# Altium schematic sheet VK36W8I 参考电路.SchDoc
size A4; PageSetup: Record=PageOptions¦CenterHorizontal=True¦CenterVertical=True¦PrintScale=1.00¦XCorrection=1.00¦YCorrection=1.00¦PrintKind=0¦BorderSize=5000000¦LeftOffset=0¦BottomOffset=0¦Orientation=2¦PaperLength=1000¦PaperWidth=1000¦Scale=100¦PaperSource=7¦PrintQuality=-4¦MediaType=1¦DitherType=10¦PaperKind=A4¦PrintScaleMode=1
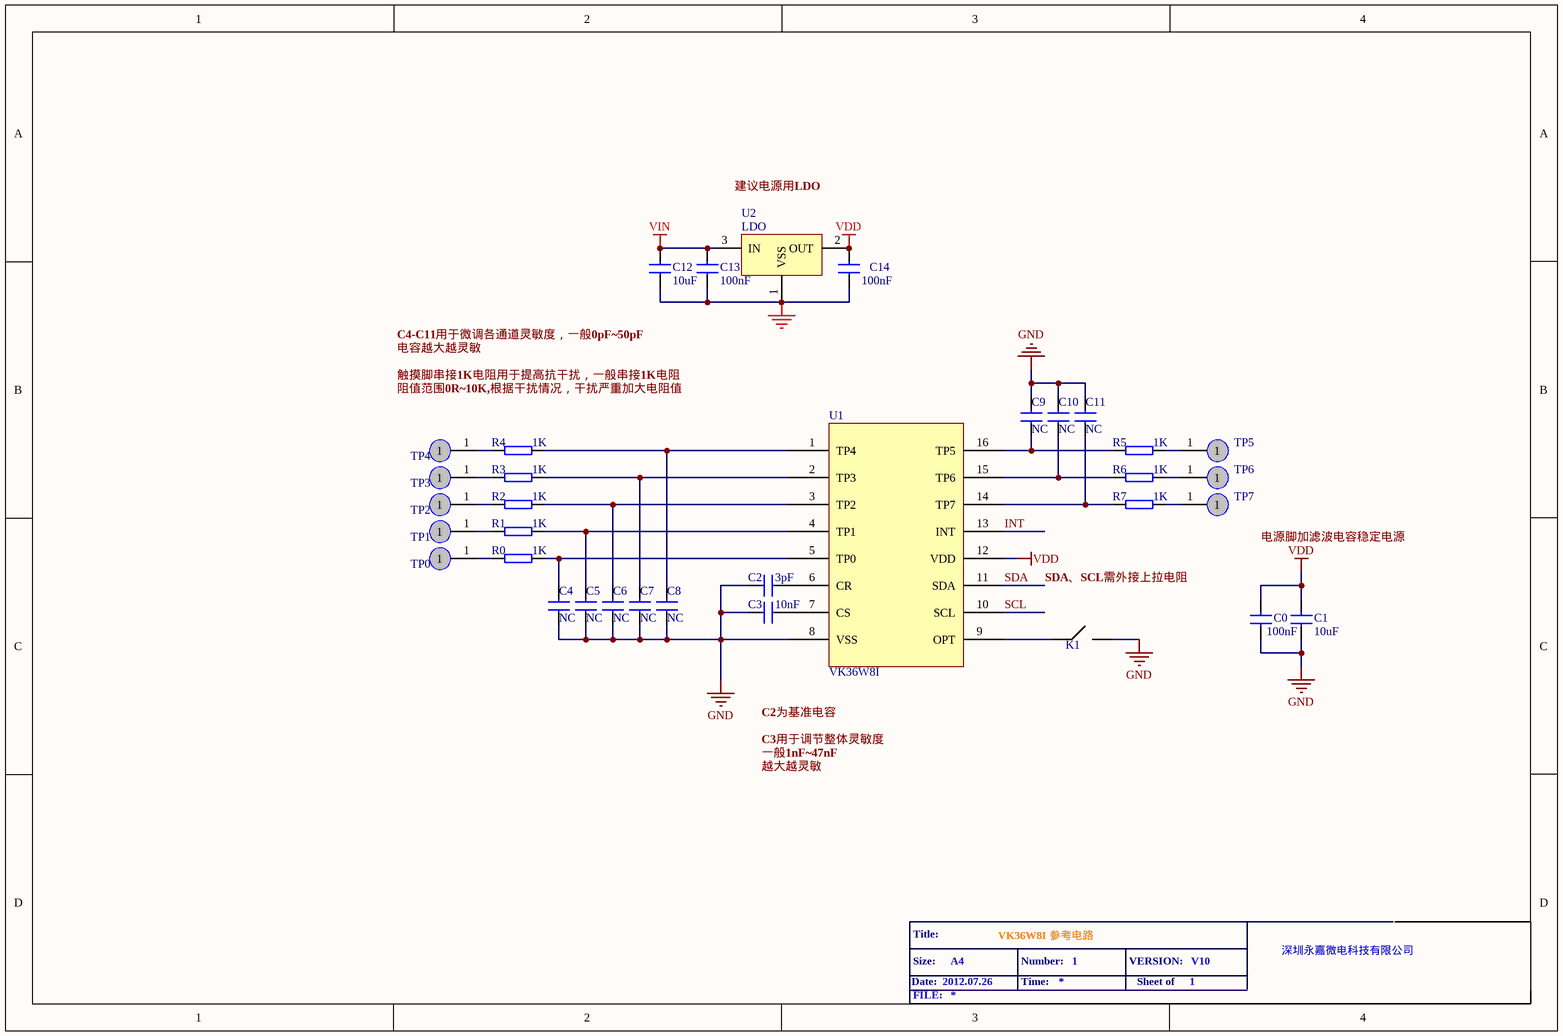
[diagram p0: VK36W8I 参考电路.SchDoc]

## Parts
C0  100nF  [0603-C]
C1  10uF  [0603-C]
C2  value 3pF  [0603-C]  (hidden comment: 10uF)
C3  value 10nF  [0603-C]  (hidden comment: 10uF)
C4  value NC  [0603-C]  (hidden comment: 10uF)
C5  value NC  [0603-C]  (hidden comment: 10uF)
C6  value NC  [0603-C]  (hidden comment: 10uF)
C7  value NC  [0603-C]  (hidden comment: 10uF)
C8  value NC  [0603-C]  (hidden comment: 10uF)
C9  value NC  [0603-C]  (hidden comment: 10uF)
C10  value NC  [0603-C]  (hidden comment: 10uF)
C11  value NC  [0603-C]  (hidden comment: 10uF)
C12  10uF  [0805-C]
C13  100nF  [0805-C]
C14  100nF  [0805-C]
K1  单刀单掷开关  (value not drawn)
R0  1K  [0603-R]
R1  1K  [0603-R]
R2  1K  [0603-R]
R3  1K  [0603-R]
R4  1K  [0603-R]
R5  1K  [0603-R]
R6  1K  [0603-R]
R7  1K  [0603-R]
TP0  TPAD  [TP-PAD0]  (value not drawn)
TP1  TPAD  [TP-PAD0]  (value not drawn)
TP2  TPAD  [TP-PAD0]  (value not drawn)
TP3  TPAD  [TP-PAD0]  (value not drawn)
TP4  TPAD  [TP-PAD0]  (value not drawn)
TP5  TPAD  [TP-PAD0]  (value not drawn)
TP6  TPAD  [TP-PAD0]  (value not drawn)
TP7  TPAD  [TP-PAD0]  (value not drawn)
U1  VK36W8I
U2  LDO  [SOT-23]

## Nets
GND: C0.2 C1.2 C2.2 C3.2 C4.1 C5.1 C6.1 C7.1 C8.1 C9.2 C10.2 C11.2 C12.2 C13.2 C14.2 U1.8(VSS) U2.1(VSS)
VDD: C0.1 C1.1 C14.1 U1.12(VDD) U2.2(OUT)
VIN: C12.1 C13.1 U2.3(IN)
INT: U1.13(INT)
SCL: U1.10(SCL)
SDA: U1.11(SDA)
NetC2_1: C2.1 U1.6(CR)
NetC3_1: C3.1 U1.7(CS)
NetC4_2: C4.2 R0.2 U1.5(TP0)
NetC5_2: C5.2 R1.1 U1.4(TP1)
NetC6_2: C6.2 R2.1 U1.3(TP2)
NetC7_2: C7.2 R3.1 U1.2(TP3)
NetC8_2: C8.2 R4.1 U1.1(TP4)
NetC9_1: C9.1 R5.1 U1.16(TP5)
NetC10_1: C10.1 R6.1 U1.15(TP6)
NetC11_1: C11.1 R7.1 U1.14(TP7)
NetR0_1: R0.1 TP0.1
NetR1_2: R1.2 TP1.1
NetR2_2: R2.2 TP2.1
NetR3_2: R3.2 TP3.1
NetR4_2: R4.2 TP4.1
NetR5_2: R5.2 TP5.1
NetR6_2: R6.2 TP6.1
NetR7_2: R7.2 TP7.1

Not connected (* = marked no-connect by the designer): U1 9(OPT)

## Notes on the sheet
- 建议电源用LDO
- 触摸脚串接1K电阻用于提高抗干扰，一般串接1K电阻
- C4-C11用于微调各通道灵敏度，一般0pF~50pF
- 电容越大越灵敏
- 阻值范围0R
  0K,根据干扰情况，干扰严重加大电阻值
- SDA、SCL需外接上拉电阻
- 电源脚加滤波电容稳定电源
- C2为基准电容
- C3用于调节整体灵敏度
- 一般1nF~47nF
- 越大越灵敏
- Date:
- Title:
- Size:
- 2012.07.26
- A4
- VK36W8I 参考电路
- Number:
- Time:
- 1
- VERSION:
- Sheet of
- V10
- 深圳永嘉微电科技有限公司
- FILE:

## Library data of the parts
C0-C14 = CAP: Capacitor
R0-R7 = RES: Resistor
TP0-TP7 = TPAD: TESTING
U2 = V6206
